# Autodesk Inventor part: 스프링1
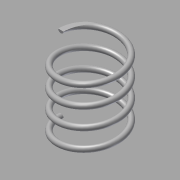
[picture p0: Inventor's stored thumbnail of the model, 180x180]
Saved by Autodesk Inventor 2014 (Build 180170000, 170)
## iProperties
Created: 2015-07
Part Number: 스프링1
Material: 강철, 연강
Document SubType Name: Modeling
Designer: Administrator
Mass: 2.74998 g
Surface Area: 9.46947 cm^2
Volume: 0.34987 cm^3
Density: 7.86 g/cm^3
Appearance: 강철
Author: Administrator
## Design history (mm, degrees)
sketch "스케치1"
  geometry: L1 (0, 0)-(8, 0); L2 (8, 0)-(8, 20.5); L3 (8, 20.5)-(0, 20.5); L4 (0, 20.5)-(0, 0); C1 r 0.75 at (8, 0)
  constraints: 8 end point, 2 parallel, 1 centre point, 1 coincident, 1 horizontal, 1 perpendicular
  dimensions: "d0" = 16 diameter of L2 L4; "d1" = 20.5 distance of L1.end L2.end (derived); "d2" = 1.5 diameter of C1
feature "코일1" sketch "스케치1" pitch "d3" = 10; turns "d5" = 4; dims "d4" = 20.5 (= d1), "d6" = 0, angle "d7" = 90 deg, angle "d8" = 90 deg, "d9" = 0, "d10" = 0
node "작업 평면1"
sketch "스케치2"
  geometry: L1 (-0.75, 0)-(0.75, 0) reference; 1 further point
  constraints: 1 horizontal alignment
extrude "돌출1" cut sketch "스케치2" stored distance "d12" = 10; taper "d13" = 0 deg
node "작업 평면2"
sketch "스케치3"
  geometry: L1 (7.25, 0)-(8.75, 0) reference; 1 further point
  constraints: 1 horizontal alignment
extrude "돌출2" cut sketch "스케치3" stored distance "d15" = 10; taper "d16" = 0 deg
node "솔리드1"
node "절단 모서리 투영1"
node "절단 모서리 투영2"
other parameters: "d11" = 90 deg, "d14" = 90 deg
